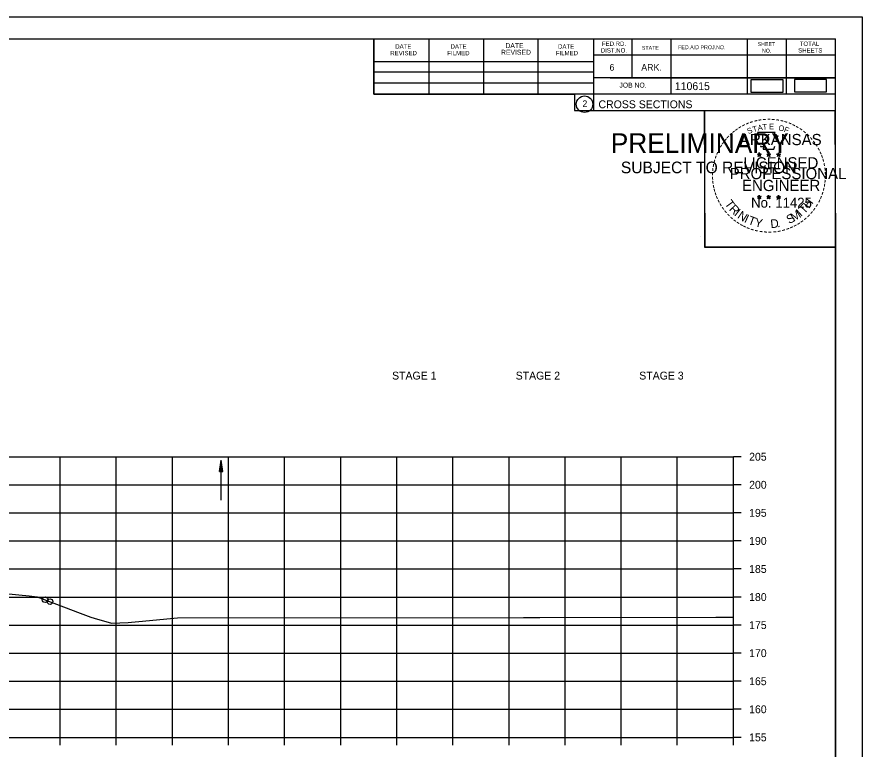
# Model space of a CAD drawing. Extents: x 1372132 to 1372465, y 380083 to 381790.
# Drawn here: x 1372314.3 to 1372464.9, y 380379.7 to 380510.2 of the extents above; entities that cross this region are included whole.
import ezdxf

# ---------------------------------------------------------------- set-up
doc = ezdxf.new("R2010")
doc.units = 0
for name, color, linetype in [('R_Axis', 7, 'Continuous'), ('R_Axis Annot', 7, 'Continuous'), ('R_Border', 7, 'Continuous'), ('R_Border PE', 7, 'Continuous'), ('R_Border Prem', 7, 'Continuous'), ('R_Dimension', 7, 'Continuous'), ('R_Draft', 7, 'Continuous'), ('R_Erosion', 7, 'Continuous'), ('R_Exist Surface', 7, 'Continuous'), ('R_Grid', 7, 'Continuous'), ('R_No Plot', 7, 'Continuous')]:
    doc.layers.add(name, color=color, linetype=linetype)

msp = doc.modelspace()

# ---------------------------------------------------------------- linework, layer by layer
at = {"layer": 'R_Axis'}
for p, q in [((1372442.01, 380381.81), (1372442.01, 380431.81)), ((1372443.41, 380431.81), (1372442.01, 380431.81)), ((1372443.41, 380426.81), (1372442.01, 380426.81)), ((1372443.41, 380421.81), (1372442.01, 380421.81)), ((1372443.41, 380416.81), (1372442.01, 380416.81)), ((1372443.41, 380411.81), (1372442.01, 380411.81)), ((1372443.41, 380406.81), (1372442.01, 380406.81)), ((1372443.41, 380401.81), (1372442.01, 380401.81)), ((1372443.41, 380396.81), (1372442.01, 380396.81)), ((1372443.41, 380391.81), (1372442.01, 380391.81)), ((1372443.41, 380386.81), (1372442.01, 380386.81)), ((1372162.01, 380381.81), (1372442.01, 380381.81)), ((1372322.01, 380380.41), (1372322.01, 380381.81)), ((1372332.01, 380380.41), (1372332.01, 380381.81)), ((1372342.01, 380380.41), (1372342.01, 380381.81)), ((1372352.01, 380380.41), (1372352.01, 380381.81)), ((1372362.01, 380380.41), (1372362.01, 380381.81)), ((1372372.01, 380380.41), (1372372.01, 380381.81)), ((1372382.01, 380380.41), (1372382.01, 380381.81)), ((1372392.01, 380380.41), (1372392.01, 380381.81)), ((1372402.01, 380380.41), (1372402.01, 380381.81)), ((1372412.01, 380380.41), (1372412.01, 380381.81)), ((1372422.01, 380380.41), (1372422.01, 380381.81)), ((1372432.01, 380380.41), (1372432.01, 380381.81)), ((1372442.01, 380380.41), (1372442.01, 380381.81)), ((1372443.41, 380381.81), (1372442.01, 380381.81))]:
    msp.add_line(p, q, dxfattribs=at)
at = {"layer": 'R_Border'}
for p, q in [((1372144.01, 380506.27), (1372460.19, 380506.27)), ((1372377.93, 380496.39), (1372377.93, 380506.27)), ((1372417.09, 380506.27), (1372417.09, 380493.47)), ((1372423.93, 380506.27), (1372423.93, 380499.33)), ((1372430.87, 380506.27), (1372430.87, 380496.39)), ((1372444.45, 380506.27), (1372444.45, 380496.39)), ((1372451.39, 380506.27), (1372451.39, 380496.39)), ((1372460.19, 380300.81), (1372460.19, 380506.27)), ((1372387.79, 380496.39), (1372387.79, 380506.07)), ((1372397.55, 380496.39), (1372397.55, 380506.07)), ((1372407.23, 380496.39), (1372407.23, 380506.07)), ((1372460.19, 380503.33), (1372417.09, 380503.33)), ((1372460.19, 380503.35), (1372460.19, 380503.35)), ((1372377.93, 380502.25), (1372417.09, 380502.25)), ((1372377.93, 380500.39), (1372417.09, 380500.39)), ((1372460.19, 380499.33), (1372417.09, 380499.33)), ((1372420.05, 380499.33), (1372460.19, 380499.33)), ((1372377.93, 380496.39), (1372377.93, 380498.45)), ((1372377.93, 380498.45), (1372417.09, 380498.45)), ((1372460.19, 380496.39), (1372377.93, 380496.39)), ((1372417.09, 380493.47), (1372460.19, 380493.47))]:
    msp.add_line(p, q, dxfattribs=at)
msp.add_circle((1372415.48, 380494.61), 1.47, dxfattribs=at)
at = {"layer": 'R_Border PE'}
for p, q in [((1372446.28, 380485.73), (1372446.63, 380485.62)), ((1372446.28, 380485.73), (1372446.53, 380485.68)), ((1372446.28, 380485.73), (1372446.52, 380485.6)), ((1372446.41, 380485.32), (1372446.63, 380485.62)), ((1372446.41, 380485.32), (1372446.54, 380485.56)), ((1372446.41, 380485.32), (1372446.63, 380485.54)), ((1372446.63, 380485.98), (1372446.59, 380485.73)), ((1372446.63, 380485.62), (1372446.63, 380485.98)), ((1372446.63, 380485.98), (1372446.68, 380485.73)), ((1372446.98, 380485.73), (1372446.63, 380485.62)), ((1372446.84, 380485.32), (1372446.63, 380485.62)), ((1372446.84, 380485.32), (1372446.63, 380485.53)), ((1372446.98, 380485.73), (1372446.69, 380485.68)), ((1372446.84, 380485.32), (1372446.7, 380485.61)), ((1372446.98, 380485.73), (1372446.77, 380485.62)), ((1372447.95, 380485.73), (1372448.3, 380485.62)), ((1372447.95, 380485.73), (1372448.2, 380485.68)), ((1372447.95, 380485.73), (1372448.19, 380485.6)), ((1372448.08, 380485.32), (1372448.3, 380485.62)), ((1372448.08, 380485.32), (1372448.21, 380485.56)), ((1372448.08, 380485.32), (1372448.3, 380485.54)), ((1372448.3, 380485.98), (1372448.26, 380485.73)), ((1372448.3, 380485.62), (1372448.3, 380485.98)), ((1372448.3, 380485.98), (1372448.35, 380485.73)), ((1372448.65, 380485.73), (1372448.3, 380485.62)), ((1372448.51, 380485.32), (1372448.3, 380485.62)), ((1372448.51, 380485.32), (1372448.3, 380485.53)), ((1372448.65, 380485.73), (1372448.36, 380485.68)), ((1372448.51, 380485.32), (1372448.37, 380485.61)), ((1372448.65, 380485.73), (1372448.44, 380485.62)), ((1372449.71, 380485.71), (1372450.06, 380485.6)), ((1372449.71, 380485.71), (1372449.97, 380485.67)), ((1372449.71, 380485.71), (1372449.95, 380485.59)), ((1372449.85, 380485.31), (1372450.06, 380485.6)), ((1372449.85, 380485.31), (1372449.97, 380485.55)), ((1372449.85, 380485.31), (1372450.06, 380485.52)), ((1372450.06, 380485.97), (1372450.02, 380485.72)), ((1372450.06, 380485.6), (1372450.06, 380485.97)), ((1372450.06, 380485.97), (1372450.11, 380485.72)), ((1372450.41, 380485.71), (1372450.06, 380485.6)), ((1372450.28, 380485.31), (1372450.06, 380485.6)), ((1372450.28, 380485.31), (1372450.06, 380485.52)), ((1372450.41, 380485.71), (1372450.12, 380485.67)), ((1372450.28, 380485.31), (1372450.14, 380485.6)), ((1372450.41, 380485.71), (1372450.21, 380485.61)), ((1372446.28, 380478.15), (1372446.62, 380478.04)), ((1372446.28, 380478.15), (1372446.53, 380478.11)), ((1372446.28, 380478.15), (1372446.51, 380478.03)), ((1372446.41, 380477.75), (1372446.62, 380478.04)), ((1372446.41, 380477.75), (1372446.53, 380477.99)), ((1372446.41, 380477.75), (1372446.62, 380477.96)), ((1372446.62, 380478.41), (1372446.58, 380478.16)), ((1372446.62, 380478.04), (1372446.62, 380478.41)), ((1372446.62, 380478.41), (1372446.67, 380478.16)), ((1372446.97, 380478.15), (1372446.62, 380478.04)), ((1372446.84, 380477.75), (1372446.62, 380478.04)), ((1372446.84, 380477.75), (1372446.62, 380477.96)), ((1372446.97, 380478.15), (1372446.69, 380478.1)), ((1372446.84, 380477.75), (1372446.7, 380478.04)), ((1372446.97, 380478.15), (1372446.77, 380478.05)), ((1372447.94, 380478.15), (1372448.29, 380478.04)), ((1372447.94, 380478.15), (1372448.2, 380478.11)), ((1372447.94, 380478.15), (1372448.18, 380478.03)), ((1372448.08, 380477.75), (1372448.29, 380478.04)), ((1372448.08, 380477.75), (1372448.2, 380477.99)), ((1372448.08, 380477.75), (1372448.29, 380477.96)), ((1372448.29, 380478.41), (1372448.25, 380478.16)), ((1372448.29, 380478.04), (1372448.29, 380478.41)), ((1372448.29, 380478.41), (1372448.34, 380478.16)), ((1372448.64, 380478.15), (1372448.29, 380478.04)), ((1372448.51, 380477.75), (1372448.29, 380478.04)), ((1372448.51, 380477.75), (1372448.29, 380477.96)), ((1372448.64, 380478.15), (1372448.35, 380478.1)), ((1372448.51, 380477.75), (1372448.37, 380478.04)), ((1372448.64, 380478.15), (1372448.44, 380478.05)), ((1372449.71, 380478.14), (1372450.06, 380478.03)), ((1372449.71, 380478.14), (1372449.96, 380478.1)), ((1372449.71, 380478.14), (1372449.95, 380478.02)), ((1372449.84, 380477.74), (1372450.06, 380478.03)), ((1372449.84, 380477.74), (1372449.97, 380477.98)), ((1372449.84, 380477.74), (1372450.06, 380477.95)), ((1372450.06, 380478.4), (1372450.02, 380478.15)), ((1372450.06, 380478.03), (1372450.06, 380478.4)), ((1372450.06, 380478.4), (1372450.11, 380478.15)), ((1372450.41, 380478.14), (1372450.06, 380478.03)), ((1372450.27, 380477.74), (1372450.06, 380478.03)), ((1372450.27, 380477.74), (1372450.06, 380477.95)), ((1372450.41, 380478.14), (1372450.12, 380478.09)), ((1372450.27, 380477.74), (1372450.14, 380478.03)), ((1372450.41, 380478.14), (1372450.2, 380478.04))]:
    msp.add_line(p, q, dxfattribs=at)
for points in [[(1372446.32, 380489.6), (1372446.59, 380488.78)], [(1372449.83, 380488.68), (1372449.97, 380488.97), (1372449.29, 380488.94), (1372449.44, 380489.6), (1372446.32, 380489.6)], [(1372446.81, 380487.18), (1372446.81, 380487.09), (1372447.38, 380487.08), (1372447.32, 380486.6), (1372449.19, 380486.6), (1372449.39, 380487.14)], [(1372446.63, 380485.98), (1372446.84, 380485.32), (1372446.28, 380485.73), (1372446.98, 380485.73), (1372446.41, 380485.32), (1372446.63, 380485.98)], [(1372448.3, 380485.98), (1372448.51, 380485.32), (1372447.95, 380485.73), (1372448.65, 380485.73), (1372448.08, 380485.32), (1372448.3, 380485.98)], [(1372450.06, 380485.97), (1372450.28, 380485.31), (1372449.71, 380485.71), (1372450.41, 380485.71), (1372449.85, 380485.31), (1372450.06, 380485.97)], [(1372446.62, 380478.41), (1372446.84, 380477.75), (1372446.28, 380478.15), (1372446.97, 380478.15), (1372446.41, 380477.75), (1372446.62, 380478.41)], [(1372448.29, 380478.41), (1372448.51, 380477.75), (1372447.94, 380478.15), (1372448.64, 380478.15), (1372448.08, 380477.75), (1372448.29, 380478.41)], [(1372450.06, 380478.4), (1372450.27, 380477.74), (1372449.71, 380478.14), (1372450.41, 380478.14), (1372449.84, 380477.74), (1372450.06, 380478.4)]]:
    msp.add_lwpolyline(points, dxfattribs=at)
for centre, radius in [((1372446.63, 380485.61), 0.172), ((1372446.63, 380485.61), 0.145), ((1372446.63, 380485.61), 0.116), ((1372446.63, 380485.61), 0.0991), ((1372446.63, 380485.61), 0.0747), ((1372446.63, 380485.61), 0.0495), ((1372446.63, 380485.61), 0.0296), ((1372448.3, 380485.61), 0.172), ((1372448.3, 380485.61), 0.145), ((1372448.3, 380485.61), 0.116), ((1372448.3, 380485.61), 0.0991), ((1372448.3, 380485.61), 0.0747), ((1372448.3, 380485.61), 0.0495), ((1372448.3, 380485.61), 0.0296), ((1372450.06, 380485.6), 0.172), ((1372450.06, 380485.6), 0.145), ((1372450.06, 380485.6), 0.116), ((1372450.06, 380485.6), 0.0991), ((1372450.06, 380485.6), 0.0747), ((1372450.06, 380485.6), 0.0495), ((1372450.06, 380485.6), 0.0296), ((1372446.62, 380478.04), 0.172), ((1372446.62, 380478.04), 0.145), ((1372446.62, 380478.04), 0.116), ((1372446.62, 380478.04), 0.0991), ((1372446.62, 380478.04), 0.0747), ((1372446.62, 380478.04), 0.0495), ((1372446.62, 380478.04), 0.0296), ((1372448.29, 380478.04), 0.172), ((1372448.29, 380478.04), 0.145), ((1372448.29, 380478.04), 0.116), ((1372448.29, 380478.04), 0.0991), ((1372448.29, 380478.04), 0.0747), ((1372448.29, 380478.04), 0.0495), ((1372448.29, 380478.04), 0.0296), ((1372450.06, 380478.03), 0.172), ((1372450.06, 380478.03), 0.145), ((1372450.06, 380478.03), 0.116), ((1372450.06, 380478.03), 0.0991), ((1372450.06, 380478.03), 0.0747), ((1372450.06, 380478.03), 0.0495), ((1372450.06, 380478.03), 0.0296)]:
    msp.add_circle(centre, radius, dxfattribs=at)
at = {"layer": 'R_Dimension'}
for p, q in [((1372350.42, 380429.18), (1372350.72, 380431.18)), ((1372350.42, 380429.18), (1372350.72, 380431.18)), ((1372351.02, 380429.18), (1372350.72, 380431.18)), ((1372351.02, 380429.18), (1372350.72, 380431.18)), ((1372350.47, 380429.18), (1372350.72, 380430.84)), ((1372350.47, 380429.18), (1372350.72, 380430.84)), ((1372350.52, 380429.18), (1372350.72, 380430.5)), ((1372350.52, 380429.18), (1372350.72, 380430.5)), ((1372350.57, 380429.18), (1372350.72, 380430.17)), ((1372350.57, 380429.18), (1372350.72, 380430.17)), ((1372350.62, 380429.18), (1372350.72, 380429.83)), ((1372350.62, 380429.18), (1372350.72, 380429.83)), ((1372350.67, 380429.18), (1372350.72, 380429.49)), ((1372350.67, 380429.18), (1372350.72, 380429.49)), ((1372350.97, 380429.18), (1372350.72, 380430.84)), ((1372350.97, 380429.18), (1372350.72, 380430.84)), ((1372350.92, 380429.18), (1372350.72, 380430.5)), ((1372350.92, 380429.18), (1372350.72, 380430.5)), ((1372350.87, 380429.18), (1372350.72, 380430.17)), ((1372350.87, 380429.18), (1372350.72, 380430.17)), ((1372350.82, 380429.18), (1372350.72, 380429.83)), ((1372350.82, 380429.18), (1372350.72, 380429.83)), ((1372350.77, 380429.18), (1372350.72, 380429.49)), ((1372350.77, 380429.18), (1372350.72, 380429.49)), ((1372350.42, 380429.18), (1372351.02, 380429.18)), ((1372350.42, 380429.18), (1372351.02, 380429.18))]:
    msp.add_line(p, q, dxfattribs=at)
at = {"layer": 'R_Draft'}
msp.add_line((1372350.72, 380424.04), (1372350.72, 380431.18), dxfattribs=at)
at = {"layer": 'R_Erosion'}
for points in [[(1372445.13, 380496.78), (1372450.85, 380496.78), (1372450.85, 380498.97), (1372445.13, 380498.97)], [(1372452.88, 380496.8), (1372458.59, 380496.8), (1372458.59, 380498.99), (1372452.88, 380498.99)]]:
    msp.add_lwpolyline(points, close=True, dxfattribs=at)
at = {"layer": 'R_Exist Surface'}
msp.add_lwpolyline([(1372312.21, 380407.44), (1372316.49, 380407.01), (1372317.92, 380406.87), (1372325.56, 380403.94), (1372327.49, 380403.22), (1372328.04, 380403.04), (1372331.17, 380402.18), (1372334.12, 380402.3), (1372334.71, 380402.32), (1372336.04, 380402.45), (1372342.95, 380403.12), (1372404.61, 380403.18), (1372407.53, 380403.19), (1372438.88, 380403.23), (1372442.01, 380403.23)], dxfattribs=at)
at = {"layer": 'R_Grid'}
for p, q in [((1372162.01, 380431.81), (1372442.01, 380431.81)), ((1372322.01, 380381.81), (1372322.01, 380431.81)), ((1372332.01, 380381.81), (1372332.01, 380431.81)), ((1372342.01, 380381.81), (1372342.01, 380431.81)), ((1372352.01, 380381.81), (1372352.01, 380431.81)), ((1372362.01, 380381.81), (1372362.01, 380431.81)), ((1372372.01, 380381.81), (1372372.01, 380431.81)), ((1372382.01, 380381.81), (1372382.01, 380431.81)), ((1372392.01, 380381.81), (1372392.01, 380431.81)), ((1372402.01, 380381.81), (1372402.01, 380431.81)), ((1372412.01, 380381.81), (1372412.01, 380431.81)), ((1372422.01, 380381.81), (1372422.01, 380431.81)), ((1372432.01, 380381.81), (1372432.01, 380431.81)), ((1372442.01, 380381.81), (1372442.01, 380431.81)), ((1372162.01, 380426.81), (1372442.01, 380426.81)), ((1372162.01, 380421.81), (1372442.01, 380421.81)), ((1372162.01, 380416.81), (1372442.01, 380416.81)), ((1372162.01, 380411.81), (1372442.01, 380411.81)), ((1372162.01, 380406.81), (1372442.01, 380406.81)), ((1372162.01, 380401.81), (1372442.01, 380401.81)), ((1372162.01, 380396.81), (1372442.01, 380396.81)), ((1372162.01, 380391.81), (1372442.01, 380391.81)), ((1372162.01, 380386.81), (1372442.01, 380386.81)), ((1372162.01, 380381.81), (1372442.01, 380381.81))]:
    msp.add_line(p, q, dxfattribs=at)
at = {"layer": 'R_No Plot'}
for p, q in [((1372131.61, 380510.17), (1372464.95, 380510.17)), ((1372436.23, 380471.02), (1372436.23, 380471.02))]:
    msp.add_line(p, q, dxfattribs=at)
for points in [[(1372131.61, 380510.17), (1372464.95, 380510.17), (1372464.95, 380296.83), (1372131.61, 380296.83)], [(1372377.93, 380506.27), (1372377.93, 380496.39), (1372413.67, 380496.39), (1372413.67, 380493.47), (1372436.87, 380493.47), (1372436.87, 380469.14), (1372460.19, 380469.14), (1372460.19, 380300.81), (1372144.01, 380300.81), (1372144.01, 380506.27)], [(1372436.87, 380493.47), (1372460.07, 380493.47), (1372460.19, 380469.14), (1372436.99, 380469.14)]]:
    msp.add_lwpolyline(points, close=True, dxfattribs=at)
for centre in [(1372319.32, 380406.33), (1372320.21, 380405.99)]:
    msp.add_circle(centre, 0.5, dxfattribs=at)

# ---------------------------------------------------------------- texts
at = {"layer": 'R_Axis Annot'}
for s, p in [('STAGE 1', (1372381.17, 380445.56)), ('STAGE 2', (1372403.2, 380445.56)), ('STAGE 3', (1372425.23, 380445.56)), ('205', (1372444.81, 380431.11)), ('200', (1372444.81, 380426.11)), ('195', (1372444.81, 380421.11)), ('190', (1372444.81, 380416.11)), ('185', (1372444.81, 380411.11)), ('180', (1372444.81, 380406.11)), ('175', (1372444.81, 380401.11)), ('170', (1372444.81, 380396.11)), ('165', (1372444.81, 380391.11)), ('160', (1372444.81, 380386.11)), ('155', (1372444.81, 380381.11))]:
    msp.add_text(s, height=1.4, dxfattribs=at).set_placement(p)
at = {"layer": 'R_Border'}
for s, height, p in [('DATE', 0.782, (1372381.73, 380504.51)), ('DATE', 0.782, (1372391.59, 380504.51)), ('DATE', 0.879, (1372401.37, 380504.61)), ('DATE', 0.782, (1372410.75, 380504.51)), ('FED.RD.', 0.782, (1372418.57, 380504.99)), ('STATE', 0.684, (1372425.69, 380504.31)), ('FED.AID PROJ.NO.', 0.684, (1372432.15, 380504.41)), ('SHEET', 0.684, (1372446.31, 380504.99)), ('TOTAL', 0.782, (1372453.83, 380504.99)), ('REVISED', 0.782, (1372380.85, 380503.33)), ('FILMED', 0.782, (1372391.01, 380503.33)), ('REVISED', 0.879, (1372400.59, 380503.43)), ('FILMED', 0.782, (1372410.35, 380503.33)), ('DIST.NO.', 0.782, (1372418.37, 380503.81)), ('NO.', 0.684, (1372447.09, 380503.81)), ('SHEETS', 0.782, (1372453.55, 380503.81)), ('6', 1.17, (1372419.93, 380500.59)), ('ARK.', 1.172, (1372425.59, 380500.59)), ('JOB NO.', 0.879, (1372421.69, 380497.57)), ('110615', 1.4, (1372431.57, 380497.13)), ('2', 1.17, (1372415.1, 380494.12)), ('CROSS SECTIONS', 1.4, (1372417.96, 380493.9))]:
    msp.add_text(s, height=height, rotation=360, dxfattribs=at).set_placement(p)
at = {"layer": 'R_Border PE'}
for s, height, rotation, p in [('-', 1.6, 24.3072, (1372444.43, 380490.46)), ('-', 1.6, 19.1761, (1372445.07, 380490.73)), ('-', 1.6, 13.6301, (1372445.82, 380490.97)), ('-', 1.6, 10.2193, (1372446.5, 380491.13)), ('-', 1.6, 5.8968, (1372447.23, 380491.24)), ('-', 1.6, 0.1862, (1372448, 380491.32)), ('-', 1.6, 357.743, (1372448.72, 380491.3)), ('-', 1.6, 352.1617, (1372449.46, 380491.25)), ('-', 1.6, 347.2049, (1372450.18, 380491.13)), ('-', 1.6, 342.3362, (1372450.82, 380490.98)), ('-', 1.6, 337.8551, (1372451.55, 380490.76)), ('-', 1.6, 38.9507, (1372442.15, 380489)), ('-', 1.6, 36.2317, (1372442.63, 380489.38)), ('-', 1.6, 34.0636, (1372443.2, 380489.78)), ('-', 1.6, 28.7918, (1372443.8, 380490.15)), ('S', 1, 21.594, (1372444.68, 380489.28)), ('T', 1, 16.4036, (1372445.59, 380489.61)), ('A', 1, 11.2132, (1372446.42, 380489.86)), ('T', 1, 6.0228, (1372447.26, 380490.03)), ('E', 1, 0.8323, (1372448.37, 380490.14)), ('O', 1, 350.4515, (1372449.97, 380489.93)), ('F', 1, 340.0707, (1372450.93, 380489.7)), ('-', 1.6, 334.1211, (1372452.18, 380490.48)), ('-', 1.6, 329.6409, (1372452.76, 380490.2)), ('-', 1.6, 325.8627, (1372453.41, 380489.84)), ('-', 1.6, 320.5297, (1372454.02, 380489.41)), ('-', 1.6, 50.6142, (1372440.87, 380487.62)), ('-', 1.6, 48.423, (1372441.27, 380488.11)), ('-', 1.6, 42.9622, (1372441.72, 380488.59)), ('ARKANSAS', 2, 360, (1372443.17, 380487.32)), ('-', 1.6, 315.5786, (1372454.62, 380488.93)), ('-', 1.6, 309.8797, (1372455.18, 380488.38)), ('-', 1.6, 62.8713, (1372439.82, 380485.91)), ('-', 1.6, 58.0706, (1372440.13, 380486.53)), ('-', 1.6, 54.2325, (1372440.45, 380487.05)), ('-', 1.6, 306.6522, (1372455.71, 380487.77)), ('-', 1.4, 303.6753, (1372456.2, 380487.21)), ('-', 1.6, 299.6684, (1372456.51, 380486.6)), ('-', 1.6, 72.3945, (1372439.34, 380484.67)), ('-', 1.6, 67.7743, (1372439.56, 380485.3)), ('LICENSED', 2, 360, (1372443.77, 380483.17)), ('DWB', 0.01, 360, (1372446.62, 380485.61)), ('DWB', 0.01, 360, (1372448.29, 380485.61)), ('DWB', 0.01, 360, (1372450.05, 380485.6)), ('-', 1.6, 294.6628, (1372456.84, 380485.99)), ('-', 1.6, 290.5728, (1372457.1, 380485.41)), ('-', 1.6, 81.2013, (1372439.01, 380483.25)), ('-', 1.6, 75.461, (1372439.14, 380483.96)), ('-', 1.6, 285.1233, (1372457.33, 380484.83)), ('-', 1.6, 280.5493, (1372457.53, 380484.09)), ('-', 1.6, 89.0622, (1372438.91, 380481.85)), ('-', 1.6, 85.1863, (1372438.93, 380482.55)), ('PROFESSIONAL', 2, 360, (1372441.35, 380481.26)), ('-', 1.6, 276.5962, (1372457.69, 380483.32)), ('-', 1.6, 274.3301, (1372457.75, 380482.6)), ('-', 1.6, 94.1959, (1372438.94, 380481.13)), ('-', 1.6, 98.9479, (1372439.01, 380480.46)), ('ENGINEER', 2, 360, (1372443.53, 380479.14)), ('-', 1.6, 263.5172, (1372457.77, 380481.3)), ('-', 1.6, 269.9407, (1372457.79, 380481.97)), ('-', 1.6, 101.7149, (1372439.15, 380479.73)), ('-', 1.6, 105.4578, (1372439.31, 380479.13)), ('-', 1.6, 255.7626, (1372457.59, 380479.97)), ('-', 1.6, 260.9953, (1372457.7, 380480.65)), ('-', 1.6, 109.0874, (1372439.53, 380478.5)), ('-', 1.6, 114.0643, (1372439.78, 380477.91)), ('T', 1.54, 306.0406, (1372440.38, 380476.88)), ('No. 11425', 1.757, 360, (1372445.16, 380476.19)), ('DWB', 0.01, 360, (1372446.61, 380478.04)), ('DWB', 0.01, 360, (1372448.28, 380478.04)), ('DWB', 0.01, 360, (1372450.05, 380478.03)), ('H', 1.54, 54.6088, (1372455.5, 380475.92)), ('-', 1.6, 247.8887, (1372457.18, 380478.58)), ('-', 1.6, 252.8681, (1372457.4, 380479.25)), ('-', 1.6, 115.7289, (1372440.09, 380477.29)), ('-', 1.6, 120.4471, (1372440.44, 380476.7)), ('-', 1.6, 125.8934, (1372440.85, 380476.14)), ('R', 1.54, 314.005, (1372441.15, 380475.83)), ('T', 1.54, 46.6444, (1372454.61, 380474.97)), ('-', 1.6, 233.8452, (1372456.12, 380476.54)), ('-', 1.6, 239.0712, (1372456.53, 380477.19)), ('-', 1.6, 244.6197, (1372456.92, 380477.95)), ('-', 1.6, 130.7181, (1372441.31, 380475.59)), ('-', 1.6, 134.2238, (1372441.82, 380475.04)), ('I', 1.54, 321.9694, (1372442.05, 380474.9)), ('N', 1.54, 326.5002, (1372442.61, 380474.43)), ('I', 1.54, 335.3603, (1372443.82, 380473.64)), ('T', 1.54, 339.8912, (1372444.48, 380473.32)), ('S', 1.54, 26.9312, (1372451.93, 380473.24)), ('M', 1.54, 32.6563, (1372452.77, 380473.65)), ('I', 1.54, 42.1136, (1372454.05, 380474.5)), ('-', 1.6, 225.7653, (1372455.21, 380475.41)), ('-', 1.6, 231.2538, (1372455.69, 380475.98)), ('-', 1.6, 138.9338, (1372442.35, 380474.58)), ('-', 1.6, 144.6463, (1372442.91, 380474.17)), ('-', 1.6, 148.0898, (1372443.47, 380473.8)), ('-', 1.6, 151.5704, (1372444.05, 380473.48)), ('Y', 1.54, 347.8556, (1372445.7, 380472.87)), ('D', 1.54, 6.3969, (1372448.69, 380472.51)), ('-', 1.6, 207.3568, (1372453.05, 380473.7)), ('-', 1.6, 212.2491, (1372453.61, 380474.04)), ('-', 1.6, 215.7363, (1372454.14, 380474.43)), ('-', 1.6, 221.0851, (1372454.69, 380474.9)), ('-', 1.6, 154.6002, (1372444.57, 380473.23)), ('-', 1.6, 158.5612, (1372445.19, 380472.98)), ('-', 1.6, 162.7983, (1372445.88, 380472.76)), ('-', 1.6, 167.5555, (1372446.59, 380472.6)), ('-', 1.6, 173.1155, (1372447.37, 380472.49)), ('-', 1.6, 176.5183, (1372448.11, 380472.44)), ('-', 1.6, 181.5918, (1372448.86, 380472.46)), ('-', 1.6, 185.8167, (1372449.67, 380472.53)), ('-', 1.6, 191.2858, (1372450.4, 380472.66)), ('.', 1.54, 13.7642, (1372449.88, 380472.64)), ('-', 1.6, 195.4743, (1372451.13, 380472.86)), ('-', 1.6, 200.7184, (1372451.81, 380473.11)), ('-', 1.6, 204.2516, (1372452.43, 380473.38))]:
    msp.add_text(s, height=height, rotation=rotation, dxfattribs=at).set_placement(p)
at = {"layer": 'R_Border Prem'}
for s, height, p in [('PRELIMINARY', 3.5, (1372420.15, 380485.93)), ('DWB', 0.01, (1372420.89, 380487.78)), ('SUBJECT TO REVISION', 2.0751, (1372421.95, 380482.31))]:
    msp.add_text(s, height=height, rotation=360, dxfattribs=at).set_placement(p)

doc.saveas('drawing.dxf')
